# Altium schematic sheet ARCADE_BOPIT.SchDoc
size A; SheetNumber: 1; SheetTotal: 1
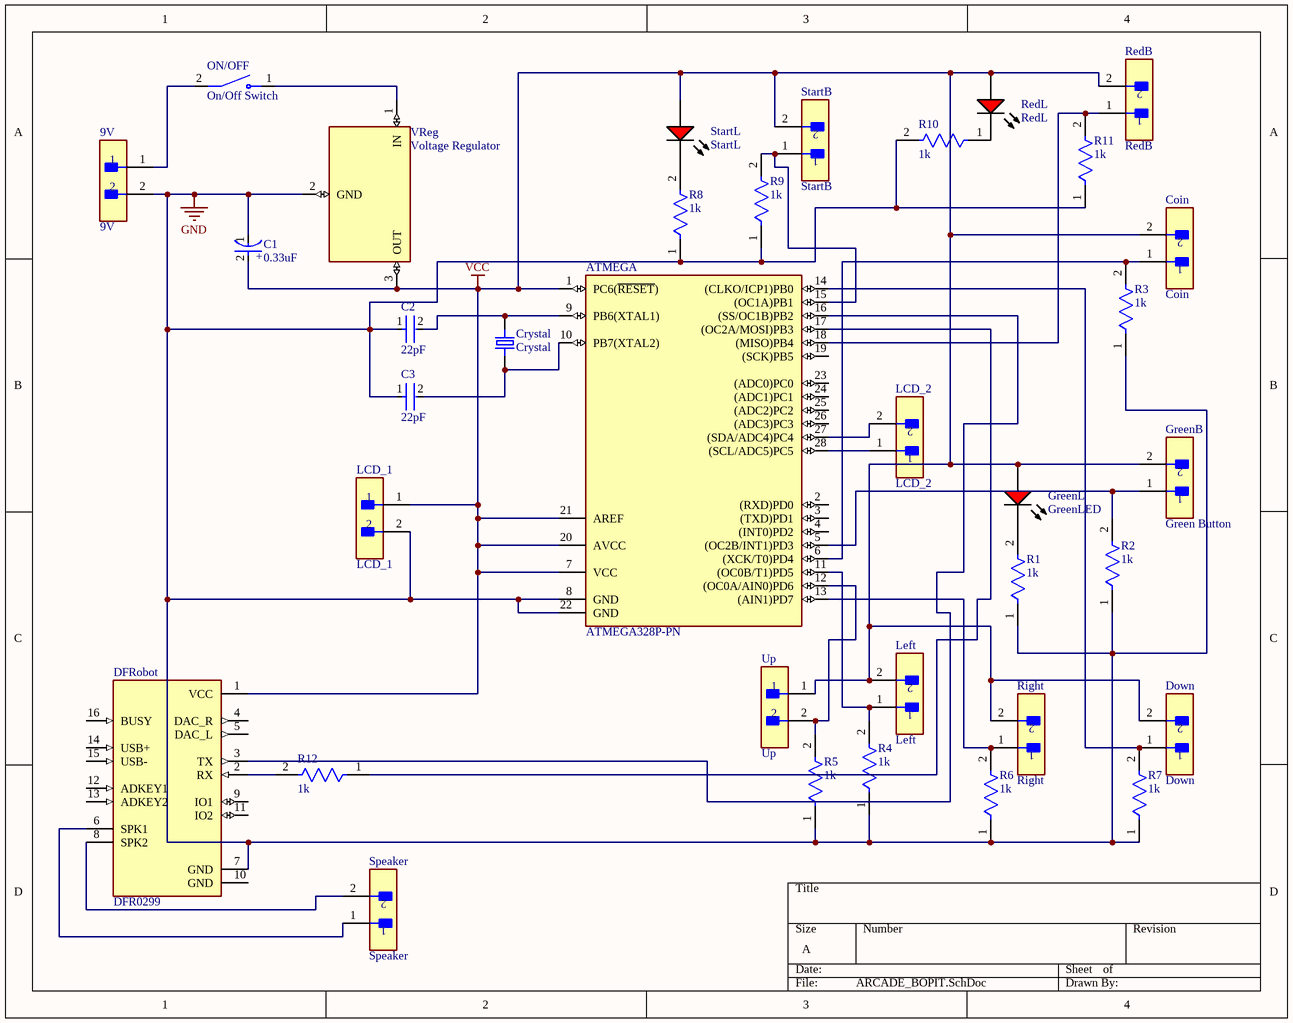
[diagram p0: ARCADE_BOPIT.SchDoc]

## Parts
9V  9V  [FP-M22-2510205-MFG]
ATMEGA  ATMEGA328P-PN  [DIL28]
C1  0.33uF  [FP-RAD-TH-D_12_5_0_5-L_20-MFG]
C2  22pF  [FP-DE6_D7_T7_F7_5_d0_6-0-MFG]
C3  22pF  [FP-DE6_D7_T7_F7_5_d0_6-0-MFG]
Coin  Coin  [FP-M22-2510205-MFG]
Crystal  Crystal  [XTAL_ECS-160-20-4X]
DFRobot  DFR0299  [MODULE_DFR0299]
Down  Down  [FP-M22-2510205-MFG]
GreenB  Green Button  [FP-M22-2510205-MFG]
GreenL  GreenLED  [AVAG-HLMP-3301-2]
LCD_1  LCD_1  [FP-M22-2510205-MFG]
LCD_2  LCD_2  [FP-M22-2510205-MFG]
Left  Left  [FP-M22-2510205-MFG]
ON/OFF  On/Off Switch  [E-SWITCH_RR511D1121]
R1  1k  [FP-MRS25-MFG]
R2  1k  [FP-MRS25-MFG]
R3  1k  [FP-MRS25-MFG]
R4  1k  [FP-MRS25-MFG]
R5  1k  [FP-MRS25-MFG]
R6  1k  [FP-MRS25-MFG]
R7  1k  [FP-MRS25-MFG]
R8  1k  [FP-MRS25-MFG]
R9  1k  [FP-MRS25-MFG]
R10  1k  [FP-MRS25-MFG]
R11  1k  [FP-MRS25-MFG]
R12  1k  [FP-MRS25-MFG]
RedB  RedB  [FP-M22-2510205-MFG]
RedL  RedL  [AVAG-HLMP-3301-2]
Right  Right  [FP-M22-2510205-MFG]
Speaker  Speaker  [FP-M22-2510205-MFG]
StartB  StartB  [FP-M22-2510205-MFG]
StartL  StartL  [AVAG-HLMP-3301-2]
Up  Up  [FP-M22-2510205-MFG]
VReg  Voltage Regulator  [TO220]

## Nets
GND: 9V.2 ATMEGA.8(GND) ATMEGA.22(GND) C1.1(C) C2.1 C3.1 DFRobot.7(GND) LCD_1.2 R1.1 R2.1 R3.1 R4.1 R5.1 R6.1 R7.1 R8.1 R9.1 R10.2 R11.1 VReg.2(GND)
VCC: ATMEGA.1(PC6(~{RESET})) ATMEGA.7(VCC) ATMEGA.20(AVCC) ATMEGA.21(AREF) C1.2(A) Coin.2 DFRobot.1(VCC) Down.2 GreenB.2 GreenL.2(A) LCD_1.1 Left.2 RedB.2 RedL.2(A) Right.2 StartB.2 StartL.2(A) Up.1 VReg.3(OUT)
Net9V_1: 9V.1 ON/OFF.2(COM)
NetATMEGA_5: ATMEGA.5((OC2B/INT1)PD3) GreenB.1 R2.2
NetATMEGA_6: ATMEGA.6((XCK/T0)PD4) Coin.1 R3.2
NetATMEGA_9: ATMEGA.9(PB6(XTAL1)) C2.2 Crystal.2
NetATMEGA_10: ATMEGA.10(PB7(XTAL2)) C3.2 Crystal.1
NetATMEGA_11: ATMEGA.11((OC0B/T1)PD5) Left.1 R4.2
NetATMEGA_12: ATMEGA.12((OC0A/AIN0)PD6) R5.2 Up.2
NetATMEGA_13: ATMEGA.13((AIN1)PD7) R6.2 Right.1
NetATMEGA_14: ATMEGA.14((CLKO/ICP1)PB0) Down.1 R7.2
NetATMEGA_15: ATMEGA.15((OC1A)PB1) R9.2 StartB.1
NetATMEGA_16: ATMEGA.16((SS/OC1B)PB2) DFRobot.3(TX)
NetATMEGA_17: ATMEGA.17((OC2A/MOSI)PB3) R12.1
NetATMEGA_18: ATMEGA.18((MISO)PB4) R11.2 RedB.1
NetATMEGA_27: ATMEGA.27((SDA/ADC4)PC4) LCD_2.2
NetATMEGA_28: ATMEGA.28((SCL/ADC5)PC5) LCD_2.1
NetDFRobot_2: DFRobot.2(RX) R12.2
NetDFRobot_6: DFRobot.6(SPK1) Speaker.1
NetDFRobot_8: DFRobot.8(SPK2) Speaker.2
NetGreenL_1: GreenL.1(K) R1.2
NetON/OFF_1: ON/OFF.1(NO) VReg.1(IN)
NetR8_2: R8.2 StartL.1(K)
NetR10_1: R10.1 RedL.1(K)

Not connected (* = marked no-connect by the designer): ATMEGA 2((RXD)PD0) 3((TXD)PD1) 4((INT0)PD2) 19((SCK)PB5) 23((ADC0)PC0) 24((ADC1)PC1) 25((ADC2)PC2) 26((ADC3)PC3); DFRobot 4(DAC_R) 5(DAC_L) 9(IO1) 10(GND) 11(IO2) 12(ADKEY1) 13(ADKEY2) 14(USB+) 15(USB-) 16(BUSY)

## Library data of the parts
9V Coin Down GreenB LCD_1 LCD_2 Left RedB Right Speaker StartB Up = CMP-15831-000005-1: CONN HEADER VERT 2POS 2MM; Manufacturer: Harwin; Manufacturer Part Number: M22-2510205; Conn Gender: Male; Current Rating: 2A; Number Of Contacts: 2; Conn Orientation: Vertical
ATMEGA = ATMEGA328P-PN: AVR AVRÂ® ATmega Microcontroller IC 8-Bit 20MHz 32KB (16K x 16) FLASH 28-PDIP; MF: Microchip
C1 = CMP-05427-000342-1: Aluminum Electrolytic Capacitors (Radial Lead Type) AEC-Q200 Qualified 2200uF ±20% 16V; Life (Hours): 5000Hour; Lead Diameter: 0.6mm; Ripple Current: 1.89A; Impedance: 29mR; Dielectric Material: Aluminium; Capacitance: 2.2mF
C2 C3 = CMP-06035-062244-1: CAP CER 1000PF 300VAC RADIAL; Lead/Base Style: Formed Leads; Capacitance: 1nF; Material: Ceramic; Tolerance: 20%; Lead Diameter: 0.6mm; Voltage Rating (AC): 300V
Crystal = ECS-160-S-4: 16MHz Â±30ppm Crystal Series 40 Ohms HC-49/US; MF: ECS Inc.
DFRobot = DFR0299: Dfplayer - a Mini Mp3 Player
GreenL RedL StartL = CMP-2000-06411-1: T-1 3/4 (5 mm) Diffused LED Lamp, 1.9 V, -40 to 100 degC, 2-Pin THD, RoHS, Bulk; Manufacturer: Avago; Forward Current: 25mA; Forward Voltage: 2.4V; Peak Wavelength: 635nm; Shape Type: Circular; High Brightness: No; Main Category: StandardLED; Test Current (It): 10mA; Dominant Wave Length: 626nm; Number of  Elements: 1; Reverse Voltage: 5V; Chip Material: GaP; Product Height (mm): 9.19mm; Lens Type: ColoredDiffused; Viewing Angle: 60deg; Emitting Color: Red; Luminous Intensity: 5.4mcd; Power Dissipation: 85W; DELETED: Compliant; Product Depth (mm): 6.1mm
ON/OFF = RR511D1121: Rocker Switch, RR5 Series, SPST,OFF-ON,Blk Rocker,I/O Legend, 20A, 125VAC, QC; MF: E-Switch
R1-R12 = CMP-02408-000051-1: RES 1K OHM 0.6W 1% AXIAL; Power Rating: 600mW; Lead Diameter: 0.6mm; Voltage Rating (DC): 350V; Resistance: 1kR; Temperature Coefficient: 50ppm/°C
VReg = LM7805: Linear Voltage Regulator IC Positive Fixed 1 Output 1.5A DDPAK/TO-263-3; MF: Texas Instruments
